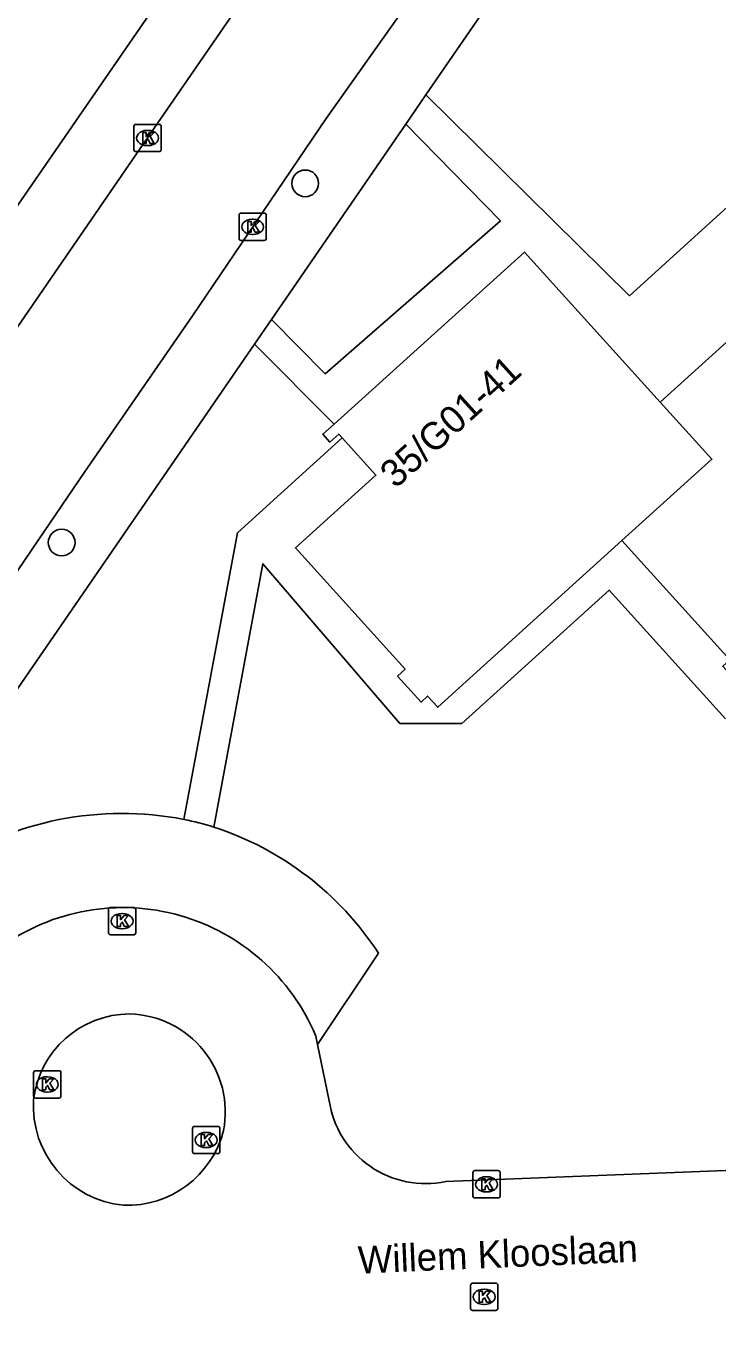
# Model space of a CAD drawing. Extents: x 160356 to 161355, y 381727 to 382845.
# Drawn here: x 160871.04 to 160896.38, y 382011.19 to 382059.16 of the extents above; entities that cross this region are included whole.
import ezdxf

# ---------------------------------------------------------------- set-up
doc = ezdxf.new("R2010")
doc.units = 0
for name, color, linetype in [('IMGEO_Boom', 7, 'Continuous'), ('IMGEO_Kolk', 7, 'Continuous'), ('IMGEO_Openbare_ruimte_label', 7, 'Continuous'), ('IMGEO_Pand', 7, 'Continuous'), ('IMGEO_Pand_nummerreeks', 7, 'Continuous'), ('IMGEO_Parkeervlak_open', 7, 'Continuous'), ('IMGEO_Rijbaan_lokaal_open', 7, 'Continuous'), ('IMGEO_Voetpad_halfverhard', 7, 'Continuous'), ('IMGEO_Voetpad_open', 7, 'Continuous')]:
    doc.layers.add(name, color=color, linetype=linetype)

msp = doc.modelspace()

# ---------------------------------------------------------------- linework, layer by layer
at = {"layer": 'IMGEO_Boom'}
for centre in [(160881.263, 382053.407), (160872.339, 382040.248)]:
    msp.add_circle(centre, 0.489, dxfattribs=at)
at = {"layer": 'IMGEO_Kolk'}
for p, q in [((160874.986, 382054.643), (160874.986, 382055.495)), ((160875.061, 382055.569), (160875.913, 382055.569)), ((160875.474, 382055.349), (160875.499, 382055.349)), ((160875.987, 382055.495), (160875.987, 382054.643)), ((160875.497, 382054.789), (160875.472, 382054.789)), ((160875.913, 382054.569), (160875.061, 382054.569)), ((160878.837, 382051.389), (160878.837, 382052.241)), ((160878.912, 382052.315), (160879.764, 382052.315)), ((160879.838, 382052.241), (160879.838, 382051.389)), ((160879.325, 382052.095), (160879.35, 382052.095)), ((160879.764, 382051.315), (160878.912, 382051.315)), ((160879.348, 382051.535), (160879.323, 382051.535)), ((160874.053, 382025.957), (160874.053, 382026.809)), ((160874.128, 382026.883), (160874.98, 382026.883)), ((160875.054, 382026.809), (160875.054, 382025.957)), ((160874.541, 382026.663), (160874.566, 382026.663)), ((160874.98, 382025.883), (160874.128, 382025.883)), ((160874.564, 382026.103), (160874.539, 382026.103)), ((160871.312, 382019.976), (160871.312, 382020.828)), ((160871.387, 382020.902), (160872.239, 382020.902)), ((160871.8, 382020.682), (160871.825, 382020.682)), ((160872.313, 382020.828), (160872.313, 382019.976)), ((160871.823, 382020.122), (160871.798, 382020.122)), ((160872.239, 382019.902), (160871.387, 382019.902)), ((160877.134, 382017.938), (160877.134, 382018.79)), ((160877.209, 382018.864), (160878.061, 382018.864)), ((160877.622, 382018.644), (160877.647, 382018.644)), ((160878.135, 382018.79), (160878.135, 382017.938)), ((160878.061, 382017.864), (160877.209, 382017.864)), ((160877.645, 382018.084), (160877.62, 382018.084)), ((160887.483, 382017.241), (160888.335, 382017.241)), ((160887.408, 382016.315), (160887.408, 382017.167)), ((160887.896, 382017.021), (160887.921, 382017.021)), ((160888.409, 382017.167), (160888.409, 382016.315)), ((160887.919, 382016.461), (160887.894, 382016.461)), ((160888.335, 382016.241), (160887.483, 382016.241)), ((160887.32, 382012.196), (160887.32, 382013.048)), ((160887.395, 382013.122), (160888.247, 382013.122)), ((160887.808, 382012.902), (160887.833, 382012.902)), ((160888.321, 382013.048), (160888.321, 382012.196)), ((160888.247, 382012.122), (160887.395, 382012.122)), ((160887.831, 382012.342), (160887.806, 382012.342))]:
    msp.add_line(p, q, dxfattribs=at)
for points in [[(160874.986, 382054.643), (160874.986, 382055.495)], [(160875.061, 382055.569), (160875.913, 382055.569)], [(160875.307, 382055.269), (160875.43, 382055.269), (160875.43, 382055.118), (160875.56, 382055.269), (160875.724, 382055.269), (160875.578, 382055.118), (160875.731, 382054.869), (160875.579, 382054.869), (160875.494, 382055.033), (160875.43, 382054.966), (160875.43, 382054.869), (160875.307, 382054.869), (160875.307, 382055.269)], [(160875.987, 382055.495), (160875.987, 382054.643)], [(160875.913, 382054.569), (160875.061, 382054.569)], [(160878.837, 382051.389), (160878.837, 382052.241)], [(160878.912, 382052.315), (160879.764, 382052.315)], [(160879.838, 382052.241), (160879.838, 382051.389)], [(160879.158, 382052.015), (160879.281, 382052.015), (160879.281, 382051.864), (160879.411, 382052.015), (160879.575, 382052.015), (160879.429, 382051.864), (160879.582, 382051.615), (160879.43, 382051.615), (160879.345, 382051.779), (160879.281, 382051.712), (160879.281, 382051.615), (160879.158, 382051.615), (160879.158, 382052.015)], [(160879.764, 382051.315), (160878.912, 382051.315)], [(160874.053, 382025.957), (160874.053, 382026.809)], [(160874.128, 382026.883), (160874.98, 382026.883)], [(160875.054, 382026.809), (160875.054, 382025.957)], [(160874.374, 382026.583), (160874.497, 382026.583), (160874.497, 382026.432), (160874.627, 382026.583), (160874.791, 382026.583), (160874.645, 382026.432), (160874.798, 382026.183), (160874.646, 382026.183), (160874.561, 382026.347), (160874.497, 382026.28), (160874.497, 382026.183), (160874.374, 382026.183), (160874.374, 382026.583)], [(160874.98, 382025.883), (160874.128, 382025.883)], [(160871.312, 382019.976), (160871.312, 382020.828)], [(160871.387, 382020.902), (160872.239, 382020.902)], [(160871.633, 382020.602), (160871.756, 382020.602), (160871.756, 382020.451), (160871.886, 382020.602), (160872.05, 382020.602), (160871.904, 382020.451), (160872.057, 382020.202), (160871.905, 382020.202), (160871.82, 382020.366), (160871.756, 382020.299), (160871.756, 382020.202), (160871.633, 382020.202), (160871.633, 382020.602)], [(160872.313, 382020.828), (160872.313, 382019.976)], [(160872.239, 382019.902), (160871.387, 382019.902)], [(160877.134, 382017.938), (160877.134, 382018.79)], [(160877.209, 382018.864), (160878.061, 382018.864)], [(160878.135, 382018.79), (160878.135, 382017.938)], [(160877.455, 382018.564), (160877.578, 382018.564), (160877.578, 382018.413), (160877.708, 382018.564), (160877.872, 382018.564), (160877.726, 382018.413), (160877.879, 382018.164), (160877.727, 382018.164), (160877.642, 382018.328), (160877.578, 382018.261), (160877.578, 382018.164), (160877.455, 382018.164), (160877.455, 382018.564)], [(160878.061, 382017.864), (160877.209, 382017.864)], [(160887.483, 382017.241), (160888.335, 382017.241)], [(160887.408, 382016.315), (160887.408, 382017.167)], [(160887.729, 382016.941), (160887.852, 382016.941), (160887.852, 382016.79), (160887.982, 382016.941), (160888.146, 382016.941), (160888, 382016.79), (160888.153, 382016.541), (160888.001, 382016.541), (160887.916, 382016.705), (160887.852, 382016.638), (160887.852, 382016.541), (160887.729, 382016.541), (160887.729, 382016.941)], [(160888.409, 382017.167), (160888.409, 382016.315)], [(160888.335, 382016.241), (160887.483, 382016.241)], [(160887.32, 382012.196), (160887.32, 382013.048)], [(160887.395, 382013.122), (160888.247, 382013.122)], [(160888.321, 382013.048), (160888.321, 382012.196)], [(160887.641, 382012.822), (160887.764, 382012.822), (160887.764, 382012.671), (160887.894, 382012.822), (160888.058, 382012.822), (160887.912, 382012.671), (160888.065, 382012.422), (160887.913, 382012.422), (160887.828, 382012.586), (160887.764, 382012.519), (160887.764, 382012.422), (160887.641, 382012.422), (160887.641, 382012.822)], [(160888.247, 382012.122), (160887.395, 382012.122)]]:
    msp.add_lwpolyline(points, dxfattribs=at)
for centre, start, end in [((160875.063, 382055.493), 91.552, 178.448), ((160875.063, 382055.493), 91.552, 178.448), ((160875.911, 382055.493), 1.552, 88.448), ((160875.911, 382055.493), 1.552, 88.448), ((160875.063, 382054.645), 181.552, 268.448), ((160875.063, 382054.645), 181.552, 268.448), ((160875.911, 382054.645), 271.552, 358.448), ((160875.911, 382054.645), 271.552, 358.448), ((160878.914, 382052.239), 91.552, 178.448), ((160878.914, 382052.239), 91.552, 178.448), ((160879.762, 382052.239), 1.552, 88.448), ((160879.762, 382052.239), 1.552, 88.448), ((160878.914, 382051.391), 181.552, 268.448), ((160878.914, 382051.391), 181.552, 268.448), ((160879.762, 382051.391), 271.552, 358.448), ((160879.762, 382051.391), 271.552, 358.448), ((160874.13, 382026.807), 91.552, 178.448), ((160874.13, 382026.807), 91.552, 178.448), ((160874.978, 382026.807), 1.552, 88.448), ((160874.978, 382026.807), 1.552, 88.448), ((160874.13, 382025.959), 181.552, 268.448), ((160874.13, 382025.959), 181.552, 268.448), ((160874.978, 382025.959), 271.552, 358.448), ((160874.978, 382025.959), 271.552, 358.448), ((160871.389, 382020.826), 91.552, 178.448), ((160871.389, 382020.826), 91.552, 178.448), ((160872.237, 382020.826), 1.552, 88.448), ((160872.237, 382020.826), 1.552, 88.448), ((160871.389, 382019.978), 181.552, 268.448), ((160871.389, 382019.978), 181.552, 268.448), ((160872.237, 382019.978), 271.552, 358.448), ((160872.237, 382019.978), 271.552, 358.448), ((160877.211, 382018.788), 91.552, 178.448), ((160877.211, 382018.788), 91.552, 178.448), ((160878.059, 382018.788), 1.552, 88.448), ((160878.059, 382018.788), 1.552, 88.448), ((160877.211, 382017.94), 181.552, 268.448), ((160877.211, 382017.94), 181.552, 268.448), ((160878.059, 382017.94), 271.552, 358.448), ((160878.059, 382017.94), 271.552, 358.448), ((160887.485, 382017.165), 91.552, 178.448), ((160887.485, 382017.165), 91.552, 178.448), ((160888.333, 382017.165), 1.552, 88.448), ((160888.333, 382017.165), 1.552, 88.448), ((160887.485, 382016.317), 181.552, 268.448), ((160887.485, 382016.317), 181.552, 268.448), ((160888.333, 382016.317), 271.552, 358.448), ((160888.333, 382016.317), 271.552, 358.448), ((160887.397, 382013.046), 91.552, 178.448), ((160887.397, 382013.046), 91.552, 178.448), ((160888.245, 382013.046), 1.552, 88.448), ((160888.245, 382013.046), 1.552, 88.448), ((160887.397, 382012.198), 181.552, 268.448), ((160887.397, 382012.198), 181.552, 268.448), ((160888.245, 382012.198), 271.552, 358.448), ((160888.245, 382012.198), 271.552, 358.448)]:
    msp.add_arc(centre, 0.0765, start, end, dxfattribs=at)
for centre, major_axis, ratio, start_param, end_param in [((160875.473, 382055.069), (-0.387, 0.002), 0.722429, 4.712389, 7.853982), ((160875.498, 382055.069), (-0.39, 0.002), 0.717154, 1.570796, 4.712389), ((160879.324, 382051.815), (-0.387, 0.002), 0.722429, 4.712389, 7.853982), ((160879.349, 382051.815), (-0.39, 0.002), 0.717154, 1.570796, 4.712389), ((160874.54, 382026.383), (-0.387, 0.002), 0.722429, 4.712389, 7.853982), ((160874.565, 382026.383), (-0.39, 0.002), 0.717154, 1.570796, 4.712389), ((160871.799, 382020.402), (-0.387, 0.002), 0.722429, 4.712389, 7.853982), ((160871.824, 382020.402), (-0.39, 0.002), 0.717154, 1.570796, 4.712389), ((160877.621, 382018.364), (-0.387, 0.002), 0.722429, 4.712389, 7.853982), ((160877.646, 382018.364), (-0.39, 0.002), 0.717154, 1.570796, 4.712389), ((160887.895, 382016.741), (-0.387, 0.002), 0.722429, 4.712389, 7.853982), ((160887.92, 382016.741), (-0.39, 0.002), 0.717154, 1.570796, 4.712389), ((160887.807, 382012.622), (-0.387, 0.002), 0.722429, 4.712389, 7.853982), ((160887.832, 382012.622), (-0.39, 0.002), 0.717154, 1.570796, 4.712389)]:
    msp.add_ellipse(centre, major_axis=major_axis, ratio=ratio, start_param=start_param, end_param=end_param, dxfattribs=at)
at = {"layer": 'IMGEO_Pand'}
for points in [[(160894.271, 382045.393), (160900.902, 382051.387), (160905.934, 382045.821)], [(160882.326, 382044.588), (160889.299, 382050.892), (160894.271, 382045.393)], [(160894.271, 382045.393), (160896.165, 382043.298), (160892.87, 382040.319)], [(160882.622, 382044.08), (160882.494, 382044.222), (160882.171, 382043.93), (160881.914, 382044.215), (160882.326, 382044.588)], [(160892.87, 382040.319), (160886.12, 382034.216), (160885.749, 382034.627), (160885.507, 382034.408), (160884.648, 382035.358), (160884.923, 382035.606), (160880.903, 382040.052), (160883.852, 382042.719), (160882.622, 382044.08)], [(160892.87, 382040.319), (160896.818, 382035.953), (160896.561, 382035.72), (160897.346, 382034.851), (160897.565, 382035.049), (160897.857, 382034.726), (160904.5, 382040.732)]]:
    msp.add_lwpolyline(points, dxfattribs=at)
at = {"layer": 'IMGEO_Parkeervlak_open'}
msp.add_lwpolyline([(160881.712, 382021.865), (160883.945, 382025.211)], dxfattribs=at)
for centre, radius, start, end in [((160874.552, 382018.402), 11.923, 79.041, 123.3238), ((160874.425, 382019.014), 11.359, 33.0604, 72.1225)]:
    msp.add_arc(centre, radius, start, end, dxfattribs=at)
at = {"layer": 'IMGEO_Rijbaan_lokaal_open'}
for points in [[(160900.454, 382091.336), (160898.732, 382088.827), (160897.579, 382087.17), (160888.911, 382074.534), (160875.487, 382055.069), (160862.667, 382036.458), (160849.849, 382017.829), (160838.733, 382001.705), (160827.599, 381985.555), (160816.487, 381969.406), (160806.996, 381955.65)], [(160811.585, 381953.706), (160812.427, 381954.838), (160843.491, 382000), (160849.506, 382008.744), (160855.258, 382017.034), (160858.854, 382022.23), (160863.124, 382028.242), (160864.448, 382030.182), (160867.631, 382034.676), (160871.484, 382040.355), (160873.174, 382042.828), (160877.127, 382048.557), (160882.027, 382055.784), (160885.092, 382060.107), (160889.498, 382066.61), (160894.202, 382073.493), (160902.442, 382085.568), (160903.558, 382087.228), (160905.012, 382089.324)]]:
    msp.add_lwpolyline(points, dxfattribs=at)
at = {"layer": 'IMGEO_Voetpad_halfverhard'}
for points in [[(160876.819, 382030.108), (160878.78, 382040.608), (160882.622, 382044.08)], [(160877.912, 382029.825), (160879.714, 382039.472), (160884.735, 382033.627), (160887.008, 382033.627), (160892.401, 382038.504), (160896.66, 382033.793)]]:
    msp.add_lwpolyline(points, dxfattribs=at)
msp.add_arc((160874.657, 382019.505), 10.821, 72.4934, 78.4741, dxfattribs=at)
at = {"layer": 'IMGEO_Voetpad_open'}
for points in [[(160885.684, 382056.644), (160895.379, 382070.732), (160897.798, 382071.659), (160908.103, 382086.516)], [(160804.86, 381957.022), (160809.509, 381963.746), (160815.556, 381972.499), (160830.024, 381993.552), (160843.658, 382013.325), (160856.447, 382031.904), (160864.216, 382043.168), (160877.531, 382062.485), (160882.102, 382069.151), (160883.88, 382071.73)], [(160885.684, 382056.644), (160893.142, 382049.287), (160900.452, 382055.921), (160900.735, 382056.178), (160899.618, 382057.218)], [(160884.945, 382055.57), (160885.684, 382056.644)], [(160880.026, 382048.423), (160884.945, 382055.57)], [(160884.945, 382055.57), (160888.414, 382052.033), (160881.997, 382046.425), (160880.026, 382048.423)], [(160879.4, 382047.514), (160880.026, 382048.423)], [(160856.025, 382013.549), (160879.4, 382047.514)], [(160882.326, 382044.588), (160879.4, 382047.514)], [(160881.649, 382022.17), (160881.712, 382021.865)], [(160882.14, 382019.803), (160881.712, 382021.865)], [(160912.804, 382017.876), (160886.414, 382016.842)]]:
    msp.add_lwpolyline(points, dxfattribs=at)
for centre, radius, start, end in [((160874.584, 382019.224), 7.654, 22.6353, 125.7522), ((160874.833, 382019.434), 3.546, 89.9753, 173.3382), ((160874.738, 382019.386), 3.596, 349.2183, 88.4509), ((160874.958, 382019.61), 3.655, 176.321, 264.3875), ((160885.674, 382020.339), 3.574, 188.621, 281.9511), ((160874.745, 382019.607), 3.636, 267.7296, 345.775)]:
    msp.add_arc(centre, radius, start, end, dxfattribs=at)

# ---------------------------------------------------------------- texts
at = {"layer": 'IMGEO_Openbare_ruimte_label'}
msp.add_text('Willem Klooslaan', height=1, rotation=2.4647, dxfattribs=at).set_placement((160883.219, 382013.467))
at = {"layer": 'IMGEO_Pand_nummerreeks'}
msp.add_text('35/G01-41', height=1, rotation=42.1181, dxfattribs=at).set_placement((160884.574, 382042.198))

doc.saveas('drawing.dxf')
